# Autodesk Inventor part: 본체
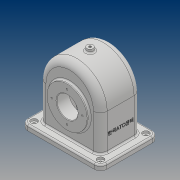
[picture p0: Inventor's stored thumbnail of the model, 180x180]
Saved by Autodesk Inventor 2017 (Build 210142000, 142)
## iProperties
Part Number: 본체
Material: 일반
Document SubType Name: Modeling
Designer: 20
Density: 1 g/cm^3
Appearance: 기본값
Author: 20
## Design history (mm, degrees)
sketch "스케치1"
  geometry: L1 (58, 0)-(58, -78); L2 (58, -78)-(-58, -78); L3 (-58, -78)-(-58, 0); A1 r 58 centre (0, 0) between (58, 0) and (-58, 0); 1 further point
  constraints: 6 end point, 2 point on circle, 2 tangent, 2 vertical, 1 centre point, 1 coincident, 1 horizontal
  dimensions: "d0" = 116 diameter of A1; "d1" = 78 distance from line of L2 point (0, 0)
extrude "돌출1" new body sketch "스케치1" stored distance "d2" = 77; taper "d3" = 0 deg
sketch "스케치3"
  geometry: L1 (52, 5.584)-(52, -85); L2 (52, -85)-(-52, -85); L3 (-52, -85)-(-52, 7.935); A1 r 52 centre (0, 0) between (52, 0) and (-52, 0); 1 further point
  constraints: 6 end point, 2 point on circle, 2 point on line, 2 tangent, 2 vertical, 1 centre point, 1 coincident, 1 horizontal
  dimensions: "d9" = 104 diameter of A1; "d10" = 85 distance from line of L2 point (0, 0)
extrude "돌출3" cut sketch "스케치3" stored distance "d11" = 67; taper "d12" = 0 deg
sketch "스케치4"
  geometry: L1 (133, -93.5)-(-17, -93.5); L2 (-17, -93.5)-(-17, 16.5); L3 (-17, 16.5)-(133, 16.5); L4 (133, 16.5)-(133, -93.5); L5 (133, -93.5)-(-17, 16.5); L6 (-17, -93.5)-(133, 16.5); L7 (0, 0)-(0, -77) reference; L8 (116, -77)-(0, -77) reference; L9 (0, 0)-(116, 0) reference; L10 (116, 0)-(116, -77) reference; 1 further point
  constraints: 12 end point, 2 midpoint, 2 parallel, 1 horizontal, 1 perpendicular
  dimensions: "d13" = 110 distance of L1.end L2.end; "d14" = 150 distance of L2.end L3.end
extrude "돌출4" join sketch "스케치4" distance "d15" = 10; taper "d16" = 0 deg
sketch "스케치5"
  geometry: L1 (-75, -78)-(75, -78) reference; C1 r 38 at (0, -13); 1 further point
  constraints: 1 centre point, 1 vertical alignment
  dimensions: "d17" = 76 diameter of C1; "d18" = 65 distance from line of C1.centre L1
extrude "돌출5" join sketch "스케치5" distance "d19" = 5; taper "d20" = 0 deg
sketch "스케치6"
  geometry: 1 further point
sketch "스케치7"
  geometry: L1 (75, 78)-(-75, 78) reference; C1 r 38 at (0, 13); 1 further point
  constraints: 1 centre point, 1 vertical alignment
  dimensions: "d21" = 76 diameter of C1; "d22" = 65 distance from line of L1 C1.centre
extrude "돌출6" join sketch "스케치7" distance "d23" = 10; taper "d24" = 0 deg
sketch "스케치8"
  geometry: C1 r 38 at (0, 13) reference; C2 r 28 at (0, 13); 1 further point
  constraints: 1 centre point, 1 coincident
  dimensions: "d25" = 56 diameter of C2
extrude "돌출7" join sketch "스케치8" distance "d26" = 14; taper "d27" = 0 deg
sketch "스케치9"
  geometry: C1 r 38 at (0, 0) reference; C2 r 20 at (0, 0); 1 further point
  constraints: 1 centre point, 1 coincident
  dimensions: "d28" = 40 diameter of C2
extrude "돌출8" cut sketch "스케치9" stored distance "d29" = 14; taper "d30" = 0 deg
node "작업 평면1"
sketch "스케치10"
  geometry: L1 (150, 0)-(0, 0) reference; L2 (150, 110)-(150, 0) reference; C1 r 6 at (75, 55); 1 further point
  constraints: 1 centre point
  dimensions: "d32" = 12 diameter of C1; "d33" = 55 distance from line of L1 C1.centre; "d34" = 75 distance from line of C1.centre L2
extrude "돌출9" join sketch "스케치10" stored distance "d35" = 14; taper "d36" = 5 deg
fillet "모깎기1" dims "d37" = 8
fillet "모깎기2" dims "d38" = 13
feature "면 기울기1" dims angle "d39" = 40 deg
fillet "모깎기3" dims "d40" = 12
sketch "스케치12"
  geometry: L1 (78, -17.5)-(78, 68.5) reference; L2 (0, -13)-(68, -13) reference; 2 further points
  constraints: 1 other
  dimensions: "d41" = 40 distance from line of L1 point (38, 25.5); "d42" = 38.5 distance from line of point (38, 25.5) L2
feature "엠보싱1" sketch "스케치12" dims "d0" = 116, "d1" = 78, "d13" = 110, "d14" = 150, "d43" = 0.5, "d44" = 0
sketch "스케치13" dims "d45" = 58
  geometry: C1 r 20 at (0, 0) reference; 3 further points
  constraints: 2 vertical alignment, 1 coincident, 2 other
hole "구멍1" sketch "스케치13" at (0, 29) diameter "d46" = 3.242; stored, may be unused: countersink angle "d50" = 90 deg, drill point angle "d52" = 118 deg; dims "d47" = 8, "d48" = 4, "d49" = 2, "d51" = 10
sketch "스케치14" dims "d56" = 58
  geometry: C1 r 38 at (0, 0) reference; 3 further points
  constraints: 2 vertical alignment, 1 coincident, 2 other
hole "구멍2" sketch "스케치14" at (0, -29) diameter "d57" = 3.242; stored, may be unused: countersink angle "d61" = 90 deg, drill point angle "d63" = 118 deg; dims "d58" = 8, "d59" = 4, "d60" = 2, "d62" = 10
hole "구멍3" diameter "d69" = 4.459; stored, may be unused: countersink angle "d73" = 90 deg, drill point angle "d75" = 118 deg; dims "d67" = 10, "d68" = 10, "d70" = 10, "d71" = 4, "d72" = 2, "d74" = 12.8
sketch "스케치16"
  geometry: A1 r 12 centre (5, 4.5) between (17, 4.5) and (5, 16.5) reference; A2 r 12 centre (5, -81.5) between (5, -93.5) and (17, -81.5) reference; A3 r 12 centre (-121, -81.5) between (-133, -81.5) and (-121, -93.5) reference; A4 r 12 centre (-121, 4.5) between (-121, 16.5) and (-133, 4.5) reference; 5 further points
  constraints: 4 coincident
hole "구멍4" sketch "스케치16" at (5, -81.5), (-121, -81.5), (5, 4.5), (-121, 4.5) diameter "d76" = 5; stored, may be unused: countersink angle "d80" = 90 deg, drill point angle "d82" = 118 deg; dims "d77" = 10, "d78" = 12, "d79" = 4, "d81" = 12.8
fillet "모깎기4" dims "d83" = 3
fillet "모깎기5" dims "d84" = 3
fillet "모깎기6" dims "d85" = 3
fillet "모깎기7" dims "d86" = 3
chamfer "모따기1" distance "d87" = 1; stored, may be unused: second distance "d88" = 2, angle "d89" = 45 deg
fillet "모깎기8" dims "d90" = 3
node "솔리드1"
pattern_circular "원형 패턴1" dims angle "d54" = 360 deg
pattern_circular "원형 패턴2" dims angle "d65" = 360 deg
other parameters: "d31" = -142
